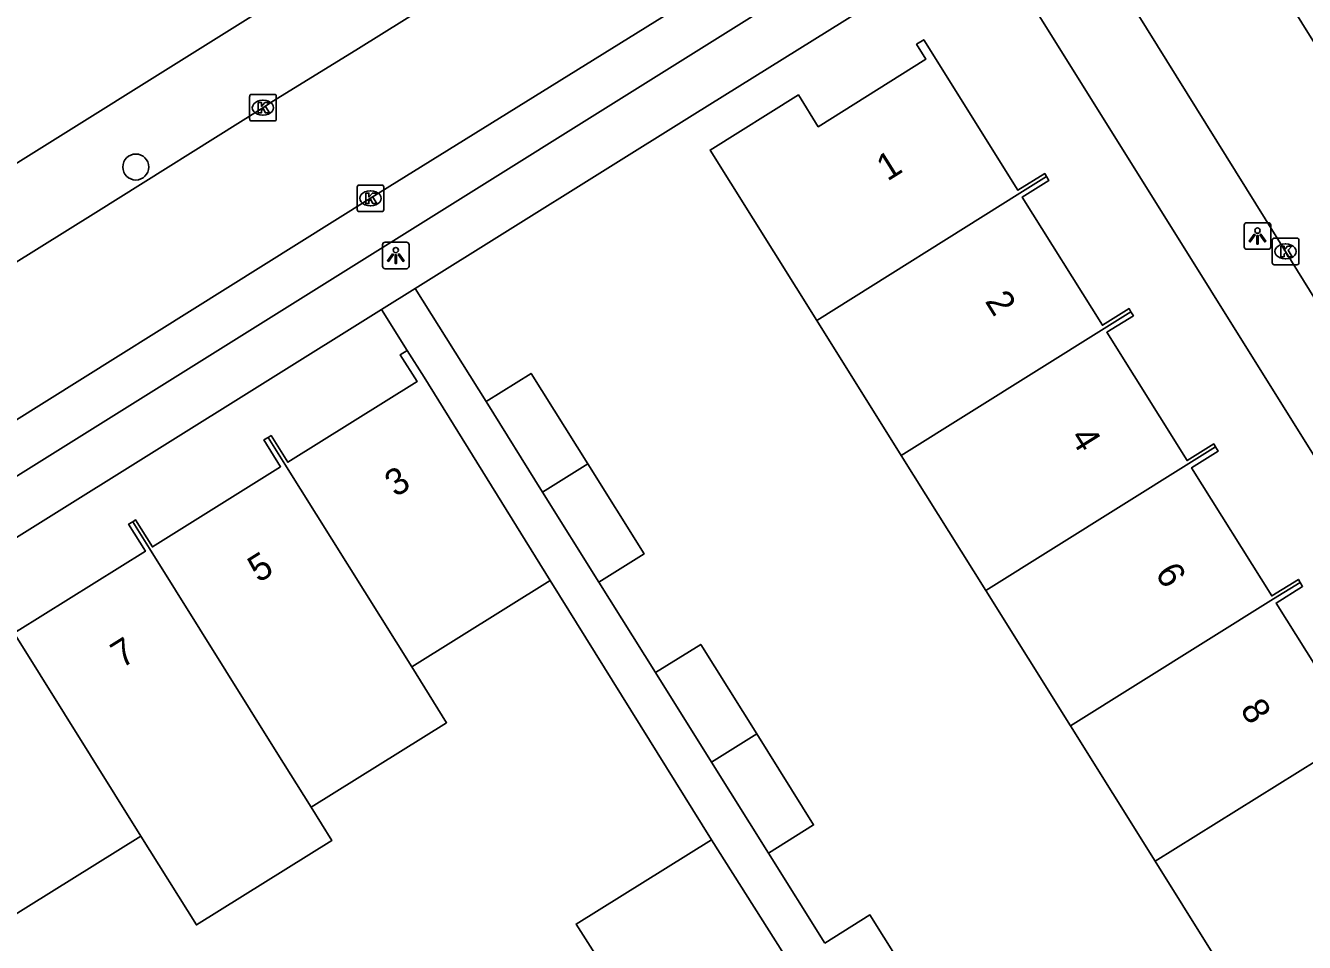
# Model space of a CAD drawing. Extents: x 158838 to 160074, y 386376 to 387776.
# Drawn here: x 159061.67 to 159109.76, y 387139.76 to 387174.25 of the extents above; entities that cross this region are included whole.
import ezdxf

# ---------------------------------------------------------------- set-up
doc = ezdxf.new("R2010")
doc.units = 0
for name, color, linetype in [('IMGEO_Boom', 7, 'Continuous'), ('IMGEO_Kolk', 7, 'Continuous'), ('IMGEO_Lichtpunt', 7, 'Continuous'), ('IMGEO_Muur', 7, 'Continuous'), ('IMGEO_Pand', 7, 'Continuous'), ('IMGEO_Pand_nummerreeks', 7, 'Continuous'), ('IMGEO_Rijbaan_lokaal_open', 7, 'Continuous'), ('IMGEO_Voetpad_open', 7, 'Continuous')]:
    doc.layers.add(name, color=color, linetype=linetype)

msp = doc.modelspace()

# ---------------------------------------------------------------- linework, layer by layer
at = {"layer": 'IMGEO_Boom'}
msp.add_circle((159065.817, 387168.93), 0.489, dxfattribs=at)
at = {"layer": 'IMGEO_Kolk'}
for p, q in [((159070.1, 387170.736), (159070.1, 387171.588)), ((159070.175, 387171.662), (159071.027, 387171.662)), ((159071.101, 387171.588), (159071.101, 387170.736)), ((159070.588, 387171.442), (159070.613, 387171.442)), ((159071.027, 387170.662), (159070.175, 387170.662)), ((159070.611, 387170.882), (159070.586, 387170.882)), ((159074.217, 387168.252), (159075.069, 387168.252)), ((159074.142, 387167.326), (159074.142, 387168.178)), ((159074.63, 387168.032), (159074.655, 387168.032)), ((159075.143, 387168.178), (159075.143, 387167.326)), ((159075.069, 387167.252), (159074.217, 387167.252)), ((159074.653, 387167.472), (159074.628, 387167.472)), ((159108.553, 387165.329), (159108.553, 387166.181)), ((159108.628, 387166.255), (159109.48, 387166.255)), ((159109.041, 387166.035), (159109.066, 387166.035)), ((159109.554, 387166.181), (159109.554, 387165.329)), ((159109.064, 387165.475), (159109.039, 387165.475)), ((159109.48, 387165.255), (159108.628, 387165.255))]:
    msp.add_line(p, q, dxfattribs=at)
for points in [[(159070.1, 387170.736), (159070.1, 387171.588)], [(159070.175, 387171.662), (159071.027, 387171.662)], [(159071.101, 387171.588), (159071.101, 387170.736)], [(159070.421, 387171.362), (159070.544, 387171.362), (159070.544, 387171.211), (159070.674, 387171.362), (159070.838, 387171.362), (159070.692, 387171.211), (159070.845, 387170.962), (159070.693, 387170.962), (159070.608, 387171.126), (159070.544, 387171.059), (159070.544, 387170.962), (159070.421, 387170.962), (159070.421, 387171.362)], [(159071.027, 387170.662), (159070.175, 387170.662)], [(159074.217, 387168.252), (159075.069, 387168.252)], [(159074.142, 387167.326), (159074.142, 387168.178)], [(159074.463, 387167.952), (159074.586, 387167.952), (159074.586, 387167.801), (159074.716, 387167.952), (159074.88, 387167.952), (159074.734, 387167.801), (159074.887, 387167.552), (159074.735, 387167.552), (159074.65, 387167.716), (159074.586, 387167.649), (159074.586, 387167.552), (159074.463, 387167.552), (159074.463, 387167.952)], [(159075.143, 387168.178), (159075.143, 387167.326)], [(159075.069, 387167.252), (159074.217, 387167.252)], [(159108.553, 387165.329), (159108.553, 387166.181)], [(159108.628, 387166.255), (159109.48, 387166.255)], [(159108.874, 387165.955), (159108.997, 387165.955), (159108.997, 387165.804), (159109.127, 387165.955), (159109.291, 387165.955), (159109.145, 387165.804), (159109.298, 387165.555), (159109.146, 387165.555), (159109.061, 387165.719), (159108.997, 387165.652), (159108.997, 387165.555), (159108.874, 387165.555), (159108.874, 387165.955)], [(159109.554, 387166.181), (159109.554, 387165.329)], [(159109.48, 387165.255), (159108.628, 387165.255)]]:
    msp.add_lwpolyline(points, dxfattribs=at)
for centre, start, end in [((159070.177, 387171.586), 91.552, 178.448), ((159070.177, 387171.586), 91.552, 178.448), ((159071.025, 387171.586), 1.552, 88.448), ((159071.025, 387171.586), 1.552, 88.448), ((159070.177, 387170.738), 181.552, 268.448), ((159070.177, 387170.738), 181.552, 268.448), ((159071.025, 387170.738), 271.552, 358.448), ((159071.025, 387170.738), 271.552, 358.448), ((159074.219, 387168.176), 91.552, 178.448), ((159074.219, 387168.176), 91.552, 178.448), ((159075.067, 387168.176), 1.552, 88.448), ((159075.067, 387168.176), 1.552, 88.448), ((159074.219, 387167.328), 181.552, 268.448), ((159074.219, 387167.328), 181.552, 268.448), ((159075.067, 387167.328), 271.552, 358.448), ((159075.067, 387167.328), 271.552, 358.448), ((159108.63, 387166.179), 91.552, 178.448), ((159108.63, 387166.179), 91.552, 178.448), ((159109.478, 387166.179), 1.552, 88.448), ((159109.478, 387166.179), 1.552, 88.448), ((159108.63, 387165.331), 181.552, 268.448), ((159108.63, 387165.331), 181.552, 268.448), ((159109.478, 387165.331), 271.552, 358.448), ((159109.478, 387165.331), 271.552, 358.448)]:
    msp.add_arc(centre, 0.0765, start, end, dxfattribs=at)
for centre, major_axis, ratio, start_param, end_param in [((159070.587, 387171.162), (-0.387, 0.002), 0.722429, 4.712389, 7.853982), ((159070.612, 387171.162), (-0.39, 0.002), 0.717154, 1.570796, 4.712389), ((159074.629, 387167.752), (-0.387, 0.002), 0.722429, 4.712389, 7.853982), ((159074.654, 387167.752), (-0.39, 0.002), 0.717154, 1.570796, 4.712389), ((159109.04, 387165.755), (-0.387, 0.002), 0.722429, 4.712389, 7.853982), ((159109.065, 387165.755), (-0.39, 0.002), 0.717154, 1.570796, 4.712389)]:
    msp.add_ellipse(centre, major_axis=major_axis, ratio=ratio, start_param=start_param, end_param=end_param, dxfattribs=at)
at = {"layer": 'IMGEO_Lichtpunt'}
for p, q in [((159108.4, 387166.834), (159107.592, 387166.834)), ((159108.4, 387166.834), (159107.592, 387166.834)), ((159107.498, 387166.739), (159107.498, 387165.932)), ((159107.498, 387166.739), (159107.498, 387165.932)), ((159108.494, 387165.932), (159108.494, 387166.739)), ((159108.494, 387165.932), (159108.494, 387166.739)), ((159075.096, 387166.006), (159075.096, 387165.199)), ((159075.096, 387166.006), (159075.096, 387165.199)), ((159075.998, 387166.101), (159075.19, 387166.101)), ((159075.998, 387166.101), (159075.19, 387166.101)), ((159076.092, 387165.199), (159076.092, 387166.006)), ((159076.092, 387165.199), (159076.092, 387166.006)), ((159107.592, 387165.838), (159108.4, 387165.838)), ((159107.592, 387165.838), (159108.4, 387165.838)), ((159075.19, 387165.105), (159075.998, 387165.105)), ((159075.19, 387165.105), (159075.998, 387165.105))]:
    msp.add_line(p, q, dxfattribs=at)
for points in [[(159107.872, 387166.403), (159107.911, 387166.375), (159107.723, 387166.113), (159107.685, 387166.14), (159107.872, 387166.403)], [(159107.974, 387166.355), (159108.021, 387166.355), (159108.021, 387166.033), (159107.974, 387166.033), (159107.974, 387166.355)], [(159108.084, 387166.375), (159108.122, 387166.402), (159108.309, 387166.14), (159108.27, 387166.112), (159108.084, 387166.375)], [(159075.47, 387165.67), (159075.509, 387165.642), (159075.321, 387165.38), (159075.283, 387165.407), (159075.47, 387165.67)], [(159075.572, 387165.622), (159075.619, 387165.622), (159075.619, 387165.3), (159075.572, 387165.3), (159075.572, 387165.622)], [(159075.682, 387165.642), (159075.72, 387165.669), (159075.907, 387165.407), (159075.868, 387165.379), (159075.682, 387165.642)]]:
    msp.add_lwpolyline(points, dxfattribs=at)
for centre in [(159107.997, 387166.537), (159075.595, 387165.804)]:
    msp.add_circle(centre, 0.0994, dxfattribs=at)
for centre, start, end in [((159107.592, 387166.739), 90, 180), ((159107.592, 387166.739), 90, 180), ((159108.4, 387166.739), 0, 90), ((159108.4, 387166.739), 0, 90), ((159075.19, 387166.006), 90, 180), ((159075.19, 387166.006), 90, 180), ((159075.998, 387166.006), 0, 90), ((159075.998, 387166.006), 0, 90), ((159107.592, 387165.932), 180, 270), ((159107.592, 387165.932), 180, 270), ((159108.4, 387165.932), 270, 0), ((159108.4, 387165.932), 270, 360), ((159075.19, 387165.199), 180, 270), ((159075.19, 387165.199), 180, 270), ((159075.998, 387165.199), 270, 0), ((159075.998, 387165.199), 270, 360)]:
    msp.add_arc(centre, 0.0946, start, end, dxfattribs=at)
at = {"layer": 'IMGEO_Muur'}
msp.add_lwpolyline([(159076.322, 387164.356), (159086.84, 387170.925)], dxfattribs=at)
at = {"layer": 'IMGEO_Pand'}
for points in [[(159091.421, 387163.161), (159087.415, 387169.565), (159090.733, 387171.64), (159091.483, 387170.446), (159095.529, 387172.987), (159095.178, 387173.546), (159095.449, 387173.716), (159098.989, 387168.056), (159099.995, 387168.685), (159100.062, 387168.574)], [(159091.421, 387163.161), (159099.058, 387167.945), (159100.062, 387168.574)], [(159100.062, 387168.574), (159100.151, 387168.427), (159099.148, 387167.8), (159102.165, 387162.976), (159103.17, 387163.604), (159103.238, 387163.488)], [(159103.238, 387163.488), (159102.237, 387162.861), (159094.601, 387158.079)], [(159103.238, 387163.488), (159103.328, 387163.337), (159102.329, 387162.713), (159105.348, 387157.885), (159106.353, 387158.513), (159106.421, 387158.403)], [(159094.601, 387158.079), (159091.421, 387163.161)], [(159070.797, 387158.762), (159070.908, 387158.83), (159071.536, 387157.826), (159076.394, 387160.862), (159075.765, 387161.869), (159076.025, 387162.032)], [(159076.025, 387162.032), (159076.659, 387161.027), (159081.402, 387153.379)], [(159078.989, 387160.107), (159080.684, 387161.168), (159082.811, 387157.767)], [(159081.116, 387156.706), (159078.989, 387160.107)], [(159065.701, 387155.589), (159065.809, 387155.654), (159066.442, 387154.642), (159071.263, 387157.655), (159070.634, 387158.662), (159070.797, 387158.762)], [(159070.797, 387158.762), (159071.425, 387157.757), (159076.194, 387150.125)], [(159097.78, 387152.996), (159105.417, 387157.775), (159106.421, 387158.403)], [(159106.421, 387158.403), (159106.518, 387158.246), (159105.515, 387157.619), (159108.532, 387152.795), (159109.533, 387153.421), (159109.601, 387153.308)], [(159081.116, 387156.706), (159082.811, 387157.767)], [(159082.811, 387157.767), (159084.93, 387154.378), (159083.234, 387153.318)], [(159097.78, 387152.996), (159094.601, 387158.079)], [(159083.234, 387153.318), (159081.116, 387156.706)], [(159060.61, 387152.41), (159060.725, 387152.479), (159061.358, 387151.466), (159066.182, 387154.48), (159065.547, 387155.496), (159065.701, 387155.589)], [(159065.701, 387155.589), (159066.335, 387154.576), (159071.103, 387146.944), (159072.415, 387144.846)], [(159081.402, 387153.379), (159076.194, 387150.125)], [(159109.601, 387153.308), (159108.602, 387152.683), (159100.965, 387147.905)], [(159109.601, 387153.308), (159109.693, 387153.153), (159108.697, 387152.53), (159111.713, 387147.708), (159112.714, 387148.334), (159112.799, 387148.209)], [(159100.965, 387147.905), (159097.78, 387152.996)], [(159060.61, 387152.41), (159061.244, 387151.395), (159066.012, 387143.763)], [(159085.365, 387149.911), (159087.061, 387150.971), (159089.165, 387147.605)], [(159076.194, 387150.125), (159077.505, 387148.027), (159072.415, 387144.846)], [(159087.47, 387146.544), (159085.365, 387149.911)], [(159104.149, 387142.815), (159111.792, 387147.581), (159112.799, 387148.209)], [(159087.47, 387146.544), (159089.165, 387147.605)], [(159089.165, 387147.605), (159091.306, 387144.181), (159089.611, 387143.121)], [(159104.149, 387142.815), (159100.965, 387147.905)], [(159089.611, 387143.121), (159087.47, 387146.544)], [(159072.415, 387144.846), (159073.193, 387143.602), (159068.101, 387140.42), (159066.012, 387143.763)], [(159066.012, 387143.763), (159060.925, 387140.584)], [(159087.468, 387143.618), (159082.372, 387140.452), (159083.775, 387138.24)], [(159087.468, 387143.618), (159090.676, 387138.561)], [(159107.334, 387137.724), (159104.149, 387142.815)], [(159095.524, 387137.437), (159093.421, 387140.799), (159091.726, 387139.739)]]:
    msp.add_lwpolyline(points, dxfattribs=at)
at = {"layer": 'IMGEO_Rijbaan_lokaal_open'}
for points in [[(159100.153, 387189.591), (159102.608, 387185.676), (159113.156, 387168.75), (159119.526, 387158.595)], [(159017.67, 387138.025), (159020.45, 387139.768), (159022.752, 387141.221), (159025.941, 387143.234), (159032.407, 387147.264), (159035.598, 387149.268), (159041.941, 387153.237), (159045.127, 387155.222), (159051.497, 387159.204), (159054.683, 387161.192), (159055.704, 387161.843), (159061.126, 387165.228), (159064.311, 387167.216), (159070.598, 387171.161), (159070.998, 387171.415), (159074.192, 387173.39), (159080.443, 387177.304), (159083.621, 387179.294), (159087.235, 387181.54), (159089.686, 387183.094)], [(159021.266, 387134.36), (159023.941, 387136.06), (159039.749, 387145.915), (159057.1, 387156.769), (159074.638, 387167.753), (159090.182, 387177.412), (159093.424, 387179.5)], [(159115.179, 387155.878), (159109.051, 387165.756), (159101.246, 387178.309)]]:
    msp.add_lwpolyline(points, dxfattribs=at)
at = {"layer": 'IMGEO_Voetpad_open'}
for points in [[(159091.517, 387187.954), (159016.017, 387140.742), (159014.494, 387139.789)], [(159076.329, 387164.36), (159086.84, 387170.925), (159095.763, 387176.497)], [(159091.807, 387176.365), (159048.502, 387149.28)], [(159098.935, 387175.998), (159128.1, 387129.289)], [(159075.057, 387163.566), (159076.329, 387164.36)], [(159076.329, 387164.36), (159078.989, 387160.107)], [(159049.302, 387147.483), (159075.057, 387163.566)], [(159076.025, 387162.032), (159075.057, 387163.566)], [(159081.402, 387153.379), (159087.468, 387143.618)], [(159083.234, 387153.318), (159085.365, 387149.911)], [(159089.611, 387143.121), (159091.726, 387139.739)]]:
    msp.add_lwpolyline(points, dxfattribs=at)

# ---------------------------------------------------------------- texts
at = {"layer": 'IMGEO_Pand_nummerreeks'}
for s, rotation, p in [('1', 32.13, (159094.082, 387168.376)), ('2', 302.0025, (159097.728, 387163.884)), ('4', 302.0025, (159100.927, 387158.766)), ('3', 31.9982, (159075.589, 387156.491)), ('5', 31.9997, (159070.439, 387153.273)), ('6', 302.0025, (159104.124, 387153.65)), ('7', 31.9997, (159065.29, 387150.056)), ('8', 302.0025, (159107.323, 387148.53))]:
    msp.add_text(s, height=1, rotation=rotation, dxfattribs=at).set_placement(p)

doc.saveas('drawing.dxf')
